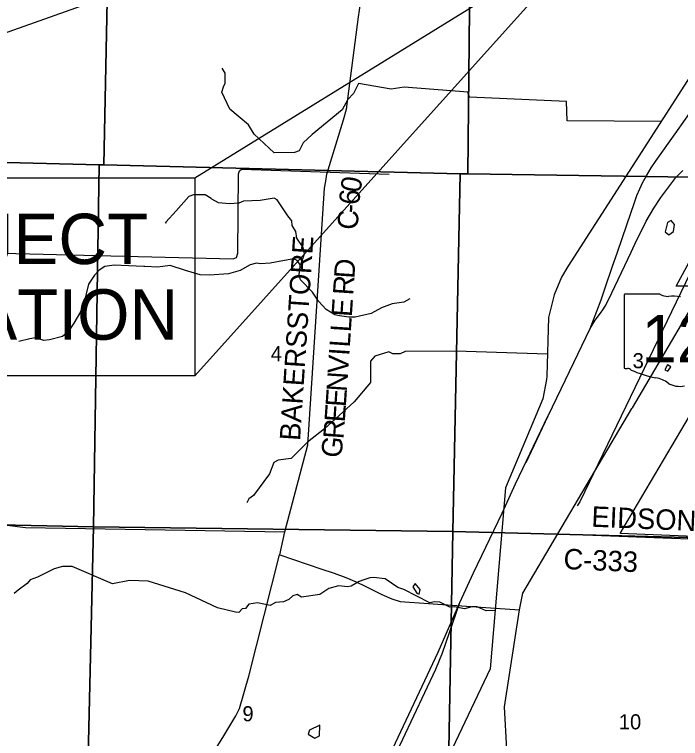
# Model space of a CAD drawing. Extents: x 0 to 68.9, y -26.1 to 22.
# Drawn here: x 2.979 to 4.831, y 15.348 to 17.359 of the extents above; entities that cross this region are included whole.
import ezdxf

# ---------------------------------------------------------------- set-up
doc = ezdxf.new("R2010")
doc.units = 0
for name, color, linetype in [('GM_X_Corporation', 7, 'Continuous'), ('GM_X_County_Road', 7, 'Continuous'), ('GM_X_County_Road_Text', 7, 'Continuous'), ('GM_X_Minor_Lake', 7, 'Continuous'), ('GM_X_Minor_River', 7, 'Continuous'), ('GM_X_Rail_Line', 7, 'Continuous'), ('GM_X_Section_Text', 7, 'Continuous'), ('GM_X_State_Location', 7, 'Continuous'), ('GM_X_State_Route', 7, 'Continuous'), ('GM_X_State_Shield', 7, 'Continuous'), ('GM_X_Township_Road', 7, 'Continuous'), ('SH_Text', 7, 'Continuous')]:
    doc.layers.add(name, color=color, linetype=linetype)

msp = doc.modelspace()

# ---------------------------------------------------------------- linework, layer by layer
at = {"layer": 'GM_X_Corporation'}
for points in [[(2.2466, 17.9726), (3.2484, 17.9456), (3.2279, 16.9417), (3.215, 16.9416), (2.2241, 16.9661)], [(3.2484, 17.9456), (4.25, 17.9235), (4.2396, 16.9168), (4.218, 16.9165), (3.2279, 16.9417)], [(4.25, 17.9235), (5.2626, 17.9001), (5.2394, 16.9012), (5.2285, 16.9015), (4.2396, 16.9168)], [(2.2241, 16.9661), (3.215, 16.9416), (3.1993, 15.9361), (2.2018, 15.9573), (2.2146, 16.9659)], [(3.2279, 16.9417), (4.218, 16.9165), (4.1977, 15.9225), (3.1993, 15.9361), (3.215, 16.9416)], [(4.2396, 16.9168), (5.2285, 16.9015), (5.2101, 15.8972), (4.1977, 15.9225), (4.218, 16.9165)], [(2.2018, 15.9573), (3.1993, 15.9361), (3.1762, 14.938), (2.1744, 14.9657)], [(3.1993, 15.9361), (4.1977, 15.9225), (4.1789, 14.914), (3.1762, 14.938)], [(4.1977, 15.9225), (5.2101, 15.8972), (5.1829, 14.8851), (4.1789, 14.914)]]:
    msp.add_lwpolyline(points, close=True, dxfattribs=at)
for points in [[(5.0687, 16.6041), (4.8187, 16.604), (4.8955, 16.7462)], [(5.214, 15.8952), (4.6626, 15.9168), (4.8916, 16.3044)]]:
    msp.add_lwpolyline(points, dxfattribs=at)
at = {"layer": 'GM_X_County_Road'}
for p, q in [((4.4899, 15.9162), (5.0318, 15.8951)), ((4.2089, 15.7174), (4.3831, 15.7051))]:
    msp.add_line(p, q, dxfattribs=at)
for points in [[(3.7173, 15.8579), (3.731, 15.9214), (3.7945, 16.1638), (3.8415, 16.8765), (3.8451, 16.8958), (3.848, 16.9159), (3.8935, 17.0662), (3.9024, 17.0964), (3.9358, 17.3531), (3.9436, 17.4095), (3.9479, 17.5832)], [(1.927, 17.1327), (1.9962, 17.1249), (2.0915, 17.1109), (2.1668, 17.101), (2.275, 17.1011), (2.3585, 17.1122), (2.4483, 17.1304), (2.5619, 17.1695), (3.6511, 17.5566)], [(1.927, 15.9512), (2.0668, 15.956), (2.529, 15.9423), (2.7651, 15.9383), (2.8115, 15.9388), (2.8572, 15.9423), (2.896, 15.9435), (2.9513, 15.9411), (3.0104, 15.9336), (3.731, 15.9214)], [(3.1578, 14.9235), (3.1692, 14.9333), (3.3487, 15.0882), (3.417, 15.1494), (3.4479, 15.1782), (3.4593, 15.1916), (3.5611, 15.3554), (3.5951, 15.4107), (3.6052, 15.4306), (3.6308, 15.5213), (3.7157, 15.8576), (3.7173, 15.8579), (3.8308, 15.8195), (3.8677, 15.807), (3.9004, 15.7954), (3.9289, 15.7828), (3.9544, 15.7713), (4.0004, 15.7479), (4.0281, 15.7353), (4.0515, 15.7285), (4.2089, 15.7174)]]:
    msp.add_lwpolyline(points, dxfattribs=at)
at = {"layer": 'GM_X_Minor_Lake'}
for points in [[(4.8046, 16.7867), (4.7943, 16.7815), (4.7883, 16.7549), (4.798, 16.7472)], [(4.798, 16.7472), (4.8114, 16.7558), (4.8143, 16.7759), (4.8046, 16.7867)], [(4.7941, 16.3854), (4.7871, 16.3718), (4.7958, 16.3686)], [(4.7958, 16.3686), (4.8039, 16.3807), (4.7941, 16.3854)], [(4.0935, 15.7782), (4.0869, 15.7691), (4.0981, 15.7519), (4.1041, 15.7487)], [(4.1041, 15.7487), (4.1066, 15.7616), (4.0935, 15.7782)], [(3.796, 15.3601), (3.814, 15.3488), (3.8274, 15.3551), (3.8278, 15.3844)], [(3.8278, 15.3844), (3.7991, 15.3707), (3.796, 15.3601)]]:
    msp.add_lwpolyline(points, dxfattribs=at)
at = {"layer": 'GM_X_Minor_River'}
for points in [[(5.2032, 17.5828), (5.134, 17.5588), (5.1121, 17.5421), (5.0972, 17.515), (5.0939, 17.5032), (5.0972, 17.4701), (5.0978, 17.4169), (5.0859, 17.3916), (5.0609, 17.373), (4.8668, 17.2013), (4.5171, 16.6592), (4.4995, 16.6291), (4.4797, 16.5807), (4.4638, 16.5175), (4.4595, 16.3547), (4.4585, 16.3449), (4.4481, 16.2914), (4.3439, 16.0443), (4.302, 15.5413), (3.617, 14.1)], [(5.0237, 17.3401), (4.9995, 17.1995), (5.0331, 17.124), (5.0533, 17.1017), (5.0403, 17.0779), (5.0084, 17.0328), (5.0023, 16.9428), (5.0093, 16.9294), (5.0102, 16.9161), (4.9337, 16.7983), (4.5504, 16.0051), (4.5433, 15.9938)], [(4.7768, 17.0617), (4.516, 17.0635), (4.5135, 17.1175), (4.2446, 17.1292), (4.2395, 17.1437), (4.0623, 17.1577), (4.0261, 17.1515), (3.9359, 17.1674), (3.9217, 17.1399), (3.9059, 17.1231), (3.8902, 17.0944), (3.8065, 17.0262), (3.7822, 17.0027), (3.7704, 16.9801), (3.7578, 16.9761), (3.7011, 16.9748), (3.6454, 17.027), (3.6299, 17.0528), (3.5778, 17.0962), (3.5558, 17.1434), (3.5602, 17.1585), (3.5646, 17.1683), (3.5647, 17.1957), (3.5569, 17.2099)], [(4.0786, 16.5692), (4.0613, 16.5601), (4.0293, 16.5552), (3.9994, 16.5445), (3.9705, 16.5285), (3.9261, 16.5186), (3.9086, 16.5179), (3.8825, 16.522), (3.8697, 16.525), (3.8461, 16.54), (3.8247, 16.563), (3.8074, 16.5874), (3.7745, 16.6221), (3.7711, 16.6366), (3.7749, 16.6651), (3.7761, 16.6673), (3.7855, 16.6941), (3.7818, 16.7117), (3.7638, 16.738), (3.7612, 16.7567), (3.7514, 16.7733), (3.7502, 16.7863), (3.7395, 16.7995), (3.7092, 16.8444), (3.7017, 16.8491), (3.6624, 16.8421), (3.6164, 16.8406), (3.6029, 16.8353), (3.577, 16.8329), (3.5463, 16.8363), (3.5284, 16.8459), (3.5257, 16.8475), (3.5093, 16.8578), (3.4774, 16.8582), (3.4643, 16.8536), (3.4288, 16.8138), (3.4002, 16.7822), (3.3998, 16.7796), (3.3987, 16.7815)], [(3.7746, 16.6631), (3.7653, 16.6756), (3.7555, 16.68), (3.7296, 16.6761), (3.6898, 16.668), (3.6636, 16.6664), (3.6518, 16.6682), (3.635, 16.6637), (3.6065, 16.6476), (3.5743, 16.6386), (3.5218, 16.6346), (3.496, 16.636), (3.4545, 16.6477), (3.412, 16.6617), (3.3777, 16.6576), (3.3416, 16.6593), (3.3393, 16.659), (3.2763, 16.6621), (3.257, 16.663), (3.231, 16.6591), (3.2148, 16.6485), (3.2016, 16.6347), (3.185, 16.6097), (3.173, 16.5597), (3.1632, 16.5334), (3.1442, 16.5015), (3.1284, 16.4779), (3.1129, 16.465), (3.0769, 16.4553), (3.0609, 16.4538), (3.0579, 16.4543), (3.0375, 16.4605), (3.0226, 16.4582), (2.9913, 16.4506)], [(4.4611, 16.4152), (4.206, 16.424), (4.065, 16.4229), (4.0519, 16.4167), (4.0314, 16.4166), (4.0197, 16.4222), (3.9815, 16.4095), (3.9691, 16.396), (3.9693, 16.3644), (3.9688, 16.3366), (3.9238, 16.283), (3.8412, 16.2079), (3.7942, 16.1706), (3.7482, 16.1254), (3.7128, 16.1214), (3.7005, 16.1144), (3.6885, 16.0826), (3.6434, 16.0225), (3.6311, 16.0131), (3.6252, 16.0026)], [(4.3156, 15.7037), (4.2908, 15.7022), (4.2651, 15.7133), (4.2503, 15.7139), (4.2305, 15.7082), (4.2028, 15.7136), (4.1899, 15.7126), (4.1616, 15.7261), (4.1472, 15.7274), (4.1342, 15.725), (4.0615, 15.7612), (4.0449, 15.7668), (4.0096, 15.791), (3.9769, 15.795), (3.967, 15.7936), (3.9502, 15.7882), (3.9376, 15.7842), (3.9157, 15.7709), (3.905, 15.7692), (3.8796, 15.7719), (3.8529, 15.7647), (3.8286, 15.7476), (3.7776, 15.7404), (3.7656, 15.7479), (3.7533, 15.7443), (3.7417, 15.7338), (3.7272, 15.7272), (3.7047, 15.7253), (3.6898, 15.7168), (3.6553, 15.7246), (3.6309, 15.7212), (3.622, 15.7084), (3.6124, 15.7078), (3.6035, 15.698), (3.594, 15.6982), (3.5441, 15.7105), (3.4547, 15.7523), (3.3508, 15.7849), (3.2987, 15.7869), (3.2518, 15.7771), (3.239, 15.783), (3.1398, 15.8254), (3.1128, 15.8259), (3.0895, 15.8194), (3.0435, 15.7955), (3.0232, 15.7886), (3.015, 15.778), (2.99, 15.7594), (2.9788, 15.7505)]]:
    msp.add_lwpolyline(points, dxfattribs=at)
at = {"layer": 'GM_X_Rail_Line'}
for points in [[(4.5792, 16.4869), (4.5981, 16.5348), (4.6097, 16.5668), (4.6208, 16.5999), (4.6405, 16.6574), (4.6551, 16.6992), (4.6813, 16.7747), (4.7025, 16.8369), (4.7094, 16.8564), (4.7174, 16.8748), (4.725, 16.8914), (4.736, 16.9113), (4.7492, 16.9332), (4.7629, 16.9533), (4.8159, 17.0272), (4.8731, 17.109)], [(4.5792, 16.4869), (4.5931, 16.5098), (4.6079, 16.529), (4.6151, 16.5385), (4.6211, 16.5485), (4.6301, 16.5667), (4.6937, 16.6989), (4.7086, 16.7308), (4.7205, 16.7548), (4.7352, 16.7846), (4.7561, 16.8207), (4.7758, 16.851), (4.7951, 16.877), (4.8174, 16.9059), (4.837, 16.9258)], [(4.4018, 16.1143), (4.463, 16.2443), (4.5108, 16.3443), (4.5792, 16.4869)], [(4.2174, 15.7254), (4.2555, 15.8084), (4.3352, 15.9739), (4.3722, 16.0554), (4.4628, 16.2449)], [(3.4501, 14.1), (3.4974, 14.2017), (3.7112, 14.6522), (3.9429, 15.1376), (4.0085, 15.2728), (4.1571, 15.5871), (4.2174, 15.7254)], [(3.4647, 14.1), (3.5422, 14.2642), (3.8062, 14.8242), (4.0587, 15.346), (4.1507, 15.5403), (4.1687, 15.5853), (4.2174, 15.7254)]]:
    msp.add_lwpolyline(points, dxfattribs=at)
at = {"layer": 'GM_X_State_Route'}
msp.add_line((4.4899, 15.9162), (4.6958, 16.2647), dxfattribs=at)
for points in [[(4.6958, 16.2647), (4.6968, 16.2664), (4.8865, 16.5875)], [(4.3831, 15.7051), (4.3927, 15.7517), (4.4899, 15.9162)], [(4.168, 14.6719), (4.2509, 14.9066), (4.3541, 15.1989), (4.3416, 15.4354), (4.3831, 15.7051)]]:
    msp.add_lwpolyline(points, dxfattribs=at)
at = {"layer": 'GM_X_State_Shield'}
for p, q in [((4.6737, 16.5788), (4.6737, 16.3787)), ((4.7735, 16.5822), (4.6769, 16.5822))]:
    msp.add_line(p, q, dxfattribs=at)
for centre, major_axis, start_param, end_param in [((4.6775, 16.5792), (0.00382, 0), 1.712693, 3.28349), ((4.7964, 16.6055), (0.037, 0), 4.042523, 4.731795), ((4.8087, 16.4699), (0.133, 0), 1.404758, 1.657858), ((4.6775, 16.3782), (0.00385, 0), 3.00124, 4.508301), ((4.6781, 16.3987), (0.0294, 0), 4.665946, 4.897461), ((4.6841, 16.3671), (0.0106, 0), 0.519207, 1.627899), ((4.8179, 16.5469), (0.2524, 0), 4.195997, 4.488961), ((4.7427, 16.2888), (0.079, 0), 0.823519, 1.323587), ((4.8281, 16.3661), (0.0501, 0), 4.026481, 4.996735)]:
    msp.add_ellipse(centre, major_axis=major_axis, ratio=0.8, start_param=start_param, end_param=end_param, dxfattribs=at)
at = {"layer": 'GM_X_Township_Road'}
msp.add_lwpolyline([(2.7179, 16.7019), (3.5874, 16.68), (3.5963, 16.684), (3.6001, 16.696), (3.6025, 16.9168), (3.605, 16.9251), (3.6108, 16.9295), (4.021, 16.9159)], dxfattribs=at)
at = {"layer": 'SH_Text'}
for p, q in [((3.4804, 16.9057), (4.5923, 17.5909)), ((4.5923, 17.5909), (3.4804, 16.3557)), ((2.3773, 16.9057), (3.4804, 16.9057)), ((3.4804, 16.9057), (3.4804, 16.3557)), ((3.4804, 16.3557), (2.3773, 16.3557))]:
    msp.add_line(p, q, dxfattribs=at)

# ---------------------------------------------------------------- texts
at = {"layer": 'GM_X_County_Road_Text'}
for s, height, rotation, p in [('0', 0.0568, 80.3697, (3.9405, 16.8622)), ('6', 0.0568, 85.0928, (3.9377, 16.8288)), ('-', 0.0568, 86.0311, (3.9361, 16.806)), ('C', 0.0568, 86.2038, (3.9331, 16.7598)), ('BAKERSSTORE', 0.056818, 86.2308, (3.7731, 16.1737)), ('D', 0.0568, 86.2046, (3.9241, 16.6244)), ('R', 0.0568, 86.2036, (3.921, 16.5779)), ('E', 0.0568, 86.205, (3.917, 16.518)), ('L', 0.0568, 86.2034, (3.9142, 16.4756)), ('L', 0.0568, 86.205, (3.9114, 16.4332)), ('I', 0.0568, 86.2036, (3.9099, 16.4099)), ('V', 0.0568, 86.2046, (3.9065, 16.36)), ('N', 0.0568, 86.2046, (3.9032, 16.3101)), ('E', 0.0568, 86.1951, (3.9004, 16.2677)), ('E', 0.0568, 86.0955, (3.8975, 16.2252)), ('R', 0.0568, 85.637, (3.8939, 16.1782)), ('G', 0.0568, 82.1827, (3.8867, 16.1249)), ('EIDSON', 0.05682, 357.5672, (4.5822, 15.9362)), ('C-333', 0.05682, 357.5217, (4.5045, 15.8186))]:
    msp.add_text(s, height=height, rotation=rotation, dxfattribs=at).set_placement(p)
at = {"layer": 'GM_X_Section_Text'}
for s, height, p in [('4', 0.0419, (3.6917, 16.3959)), ('3', 0.0419, (4.6976, 16.3764)), ('9', 0.0419, (3.613, 15.3956)), ('10', 0.04186, (4.6592, 15.3731))]:
    msp.add_text(s, height=height, rotation=0, dxfattribs=at).set_placement(p)
at = {"layer": 'GM_X_State_Location'}
msp.add_text('121', height=0.000189, rotation=0, dxfattribs=at).set_placement((4.7679, 16.4516))
at = {"layer": 'GM_X_State_Shield'}
msp.add_text('121', height=0.13184, dxfattribs=at).set_placement((4.7223, 16.3928))
at = {"layer": 'SH_Text'}
for s, p in [('PROJECT', (2.4773, 16.6657)), ('LOCATION', (2.4773, 16.4557))]:
    msp.add_text(s, height=0.14, dxfattribs=at).set_placement(p)

doc.saveas('drawing.dxf')
